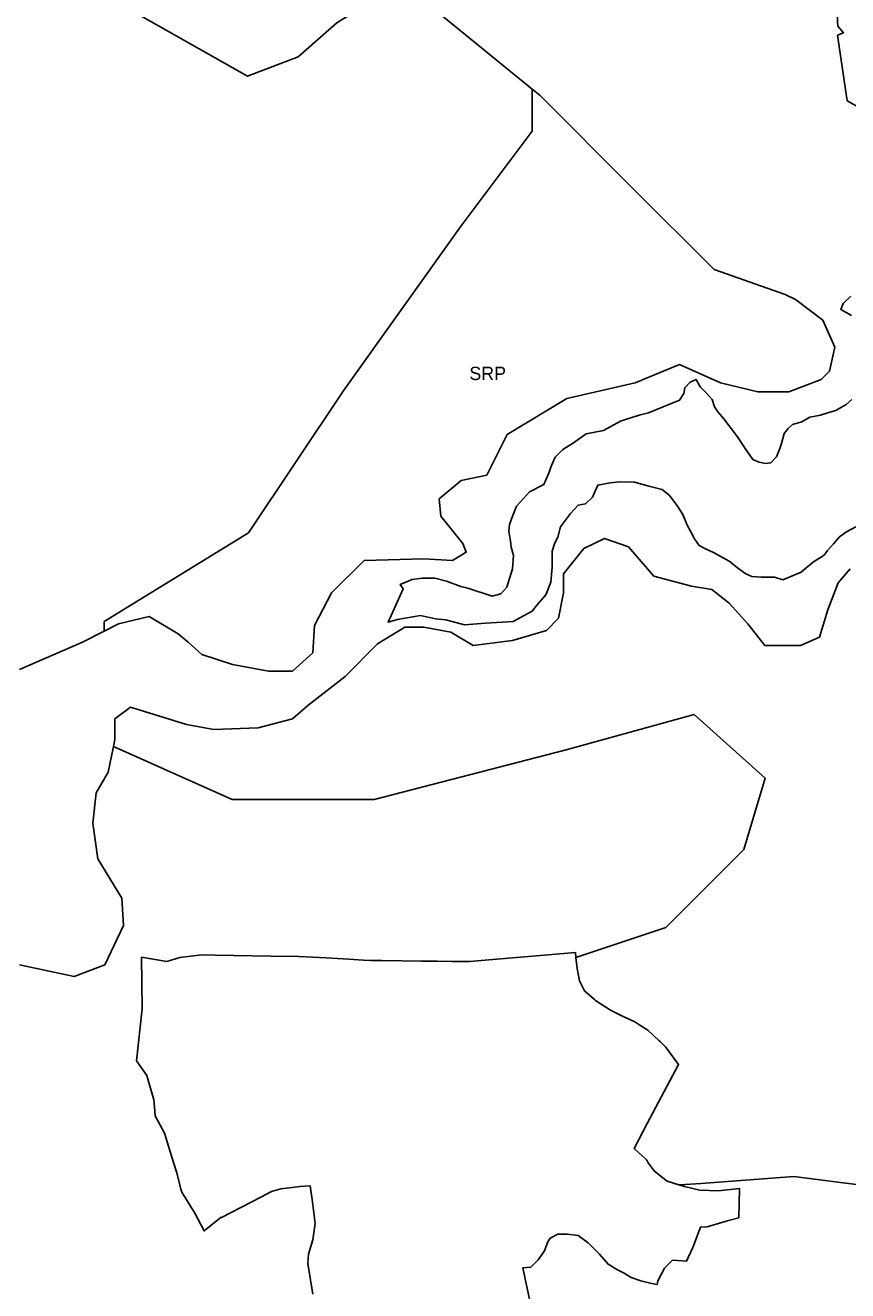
# Model space of a CAD drawing. Extents: x 598968 to 613553, y 4409678 to 4430833.
# Drawn here: x 604005 to 604746, y 4417266 to 4418405 of the extents above; entities that cross this region are included whole.
import ezdxf

# ---------------------------------------------------------------- set-up
doc = ezdxf.new("R2010")
doc.units = 0
for name, color, linetype in [("Hortal d'Oci", 7, 'Continuous'), ('Sòl Rústic Comú', 7, 'Continuous'), ('Sòl Rústic Protegit', 7, 'Continuous')]:
    doc.layers.add(name, color=color, linetype=linetype)

msp = doc.modelspace()

# ---------------------------------------------------------------- linework, layer by layer
at = {"layer": "Hortal d'Oci"}
msp.add_lwpolyline([(604460.4085, 4417252.3528), (604453.0009, 4417286.3984), (604460.2827, 4417287.1264), (604466.8363, 4417293.68), (604472.6617, 4417301.69), (604475.5743, 4417309.7), (604477.7589, 4417312.9766), (604484.6765, 4417316.6176), (604493.0505, 4417316.6176), (604502.8809, 4417315.5254), (604511.9831, 4417308.9718), (604522.1775, 4417298.7772), (604529.8233, 4417289.675), (604538.1975, 4417284.5778), (604544.3869, 4417281.6652), (604550.5763, 4417277.6602), (604559.3145, 4417274.7476), (604567.6885, 4417272.563), (604573.8609, 4417271.4738), (604573.9283, 4417271.487), (604574.6701, 4417274.6502), (604580.7801, 4417286.2202), (604587.8701, 4417293.3802), (604596.8603, 4417292.6738), (604600.5473, 4417292.3842), (604606.1601, 4417304.7102), (604613.0331, 4417323.0408), (604619.0001, 4417323.2402), (604638.3127, 4417329.1284), (604647.5515, 4417331.462), (604648.0901, 4417357.8902), (604628.9601, 4417355.7202), (604612.4101, 4417356.4702), (604598.5797, 4417359.5884), (604593.6145, 4417361.1264), (604593.5683, 4417361.1408), (604583.1387, 4417364.3716), (604577.9355, 4417368.4562), (604571.2301, 4417373.7202), (604565.9661, 4417381.0074), (604564.8291, 4417383.4706), (604563.1901, 4417384.8502), (604554.1349, 4417393.0424), (604553.3097, 4417393.789), (604553.3221, 4417393.8124), (604565.1861, 4417416.3564), (604593.3301, 4417469.5902), (604581.6239, 4417485.26), (604581.0141, 4417485.869), (604577.0349, 4417489.8438), (604575.7009, 4417491.1762), (604565.6777, 4417500.2778), (604557.6731, 4417505.5056), (604553.8319, 4417508.0144), (604553.4843, 4417508.1652), (604543.3529, 4417512.5652), (604531.9627, 4417518.4812), (604518.5181, 4417527.1454), (604517.8389, 4417527.583), (604517.4903, 4417527.8964), (604508.7267, 4417535.7746), (604504.1709, 4417544.8762), (604501.8927, 4417555.7984), (604500.8815, 4417565.7416), (604500.4301, 4417570.1818), (604475.7799, 4417568.1008), (604425.9597, 4417563.8946), (604405.0601, 4417562.1302), (604389.6199, 4417562.3126), (604376.0301, 4417562.4732), (604361.8897, 4417562.6404), (604326.0401, 4417563.0728), (604316.0219, 4417563.164), (604309.6901, 4417563.2702), (604296.3491, 4417564.2118), (604276.1201, 4417565.6396), (604251.4001, 4417566.8502), (604226.1501, 4417567.1282), (604176.1599, 4417567.9268), (604164.1701, 4417568.3602), (604144.1501, 4417565.9002), (604132.6601, 4417562.2502), (604109.8301, 4417566.0702), (604110.3121, 4417519.6512), (604105.1901, 4417472.8002), (604114.4801, 4417459.5802), (604121.0101, 4417437.6202), (604121.7467, 4417427.83), (604122.0801, 4417423.4002), (604130.4801, 4417407.5702), (604138.7155, 4417381.1888), (604141.5901, 4417371.9802), (604145.2431, 4417357.376), (604145.9401, 4417354.5902), (604157.9269, 4417335.6482), (604166.1615, 4417319.652), (604181.5201, 4417332.0002), (604181.8167, 4417331.602), (604217.3009, 4417349.9776), (604226.9183, 4417355.107), (604235.2533, 4417357.6716), (604252.5647, 4417359.595), (604261.5409, 4417360.2362), (604263.4643, 4417348.0542), (604266.0291, 4417326.2548), (604264.1055, 4417311.508), (604260.2585, 4417298.6848), (604259.6175, 4417290.3498), (604264.1055, 4417262.7798)], dxfattribs=at)
at = {"layer": 'Sòl Rústic Comú'}
for points in [[(603999.9115, 4417825.1932), (604056.7247, 4417849.6934), (604076.0375, 4417859.6934), (604076.0375, 4417868.1934), (604206.1641, 4417948.1936), (604291.2905, 4418075.6938), (604397.6673, 4418224.6942), (604461.4807, 4418309.6944), (604461.4809, 4418347.6944), (604377.0427, 4418416.1944), (604320.4797, 4418429.1942), (604285.6667, 4418407.1942), (604250.7913, 4418376.6942), (604205.1033, 4418359.194), (603943.8511, 4418507.1938)], [(604264.1055, 4417262.7798), (604259.6175, 4417290.3498), (604260.2585, 4417298.6848), (604264.1055, 4417311.508), (604266.0291, 4417326.2548), (604263.4643, 4417348.0542), (604261.5409, 4417360.2362), (604252.5647, 4417359.595), (604235.2533, 4417357.6716), (604226.9183, 4417355.107), (604217.3009, 4417349.9776), (604181.8167, 4417331.602), (604181.5201, 4417332.0002), (604166.1615, 4417319.652), (604157.9269, 4417335.6482), (604145.9401, 4417354.5902), (604145.2431, 4417357.376), (604141.5901, 4417371.9802), (604138.7155, 4417381.1888), (604130.4801, 4417407.5702), (604122.0801, 4417423.4002), (604121.7467, 4417427.83), (604121.0101, 4417437.6202), (604114.4801, 4417459.5802), (604105.1901, 4417472.8002), (604110.3121, 4417519.6512), (604109.8301, 4417566.0702), (604132.6601, 4417562.2502), (604144.1501, 4417565.9002), (604164.1701, 4417568.3602), (604176.1599, 4417567.9268), (604226.1501, 4417567.1282), (604251.4001, 4417566.8502), (604276.1201, 4417565.6396), (604296.3491, 4417564.2118), (604309.6901, 4417563.2702), (604316.0219, 4417563.164), (604326.0401, 4417563.0728), (604361.8897, 4417562.6404), (604376.0301, 4417562.4732), (604389.6199, 4417562.3126), (604405.0601, 4417562.1302), (604425.9597, 4417563.8946), (604475.7799, 4417568.1008), (604500.4301, 4417570.1818), (604500.8815, 4417565.7416), (604581.7917, 4417592.6938), (604652.1677, 4417663.194), (604671.4181, 4417727.194), (604607.3553, 4417784.694), (604492.1665, 4417752.6938), (604319.2895, 4417708.1936), (604191.2881, 4417708.1934), (604084.4747, 4417755.6934), (604079.7245, 4417732.6932), (604069.0369, 4417714.1932), (604065.9117, 4417686.6932), (604070.5367, 4417654.6932), (604092.0367, 4417619.1932), (604093.5991, 4417594.6932), (604076.6613, 4417559.1932), (604049.0361, 4417548.693), (603999.9105, 4417559.193)], [(604793.0431, 4417356.194), (604696.9797, 4417368.6938), (604613.7913, 4417362.1936), (604594.3417, 4417361.181), (604593.6117, 4417361.143), (604593.5683, 4417361.1408), (604593.6145, 4417361.1264), (604598.5797, 4417359.5884), (604612.4101, 4417356.4702), (604628.9601, 4417355.7202), (604648.0901, 4417357.8902), (604647.5515, 4417331.462), (604638.3127, 4417329.1284), (604619.0001, 4417323.2402), (604613.0331, 4417323.0408), (604606.1601, 4417304.7102), (604600.5473, 4417292.3842), (604596.8603, 4417292.6738), (604587.8701, 4417293.3802), (604580.7801, 4417286.2202), (604574.6701, 4417274.6502), (604573.9283, 4417271.487), (604573.8609, 4417271.4738), (604567.6885, 4417272.563), (604559.3145, 4417274.7476), (604550.5763, 4417277.6602), (604544.3869, 4417281.6652), (604538.1975, 4417284.5778), (604529.8233, 4417289.675), (604522.1775, 4417298.7772), (604511.9831, 4417308.9718), (604502.8809, 4417315.5254), (604493.0505, 4417316.6176), (604484.6765, 4417316.6176), (604477.7589, 4417312.9766), (604475.5743, 4417309.7), (604472.6617, 4417301.69), (604466.8363, 4417293.68), (604460.2827, 4417287.1264), (604453.0009, 4417286.3984), (604460.4085, 4417252.3528)]]:
    msp.add_lwpolyline(points, dxfattribs=at)
at = {"layer": 'Sòl Rústic Protegit'}
for points in [[(603943.8511, 4418507.1938), (604205.1033, 4418359.194), (604250.7913, 4418376.6942), (604285.6667, 4418407.1942)], [(604377.0427, 4418416.1944), (604461.4809, 4418347.6944), (604468.4809, 4418342.1944), (604551.2315, 4418259.1944), (604625.2319, 4418185.1944), (604689.2325, 4418162.6946), (604698.6077, 4418158.1946), (604723.1703, 4418139.6946), (604733.9203, 4418115.1946), (604729.2951, 4418093.6946), (604721.6075, 4418086.1944), (604692.4823, 4418075.1944), (604664.7945, 4418075.1944), (604631.0441, 4418083.1944), (604594.1689, 4418099.6944), (604554.2309, 4418083.1942), (604492.8551, 4418069.1942), (604439.1045, 4418036.694), (604420.6667, 4418000.194), (604397.6039, 4417995.194), (604377.6661, 4417978.694), (604379.1661, 4417963.194), (604399.1661, 4417938.694), (604402.2287, 4417930.694), (604389.9161, 4417923.1938), (604363.8533, 4417924.6938), (604310.1027, 4417923.1938), (604280.9147, 4417894.1938), (604265.5395, 4417864.6936), (604264.0393, 4417840.1936), (604245.6017, 4417823.6936), (604224.1015, 4417823.6936), (604191.8511, 4417829.6936), (604164.2259, 4417838.6934), (604151.9133, 4417849.6934), (604142.7257, 4417857.1934), (604116.6005, 4417872.6934), (604088.9751, 4417866.1934), (604076.0375, 4417859.6934), (604056.7247, 4417849.6934), (603999.9115, 4417825.1932)], [(604761.8589, 4418327.6948), (604745.1713, 4418337.1948), (604736.5465, 4418396.1948), (604741.7965, 4418398.1948), (604736.7339, 4418404.1948), (604736.0465, 4418414.6948)], [(604736.0465, 4418414.6948), (604736.7339, 4418404.1948), (604741.7965, 4418398.1948), (604736.5465, 4418396.1948), (604745.1713, 4418337.1948), (604761.8589, 4418327.6948)], [(604748.9205, 4418143.6946), (604739.5455, 4418149.1946), (604741.4831, 4418154.6946), (604748.5457, 4418161.1946)], [(604748.5457, 4418161.1946), (604741.4831, 4418154.6946), (604739.5455, 4418149.1946), (604748.9205, 4418143.6946)], [(604752.9199, 4417953.6944), (604744.6697, 4417949.1944), (604738.1697, 4417944.6944), (604732.9197, 4417938.1944), (604727.4821, 4417932.1944), (604724.4195, 4417928.1944), (604714.7943, 4417922.1944), (604708.2317, 4417916.6944), (604703.7943, 4417912.6944), (604687.1691, 4417905.6942), (604679.7315, 4417908.1942), (604667.7313, 4417908.1942), (604659.3563, 4417908.6942), (604653.9813, 4417911.1942), (604647.5437, 4417915.6942), (604638.9185, 4417922.6942), (604625.4809, 4417930.1942), (604616.9185, 4417934.1942), (604611.8559, 4417936.6942), (604607.7933, 4417942.6942), (604604.4183, 4417949.1942), (604600.9809, 4417955.1942), (604597.2309, 4417964.6942), (604593.0433, 4417971.1942), (604589.1683, 4417976.6942), (604584.7933, 4417982.1942), (604578.4183, 4417987.1942), (604566.5431, 4417990.1942), (604553.6055, 4417993.6942), (604540.3553, 4417994.1942), (604531.7927, 4417993.1942), (604520.5427, 4417991.1942), (604515.9175, 4417980.1942), (604509.4799, 4417974.194), (604502.7923, 4417973.194), (604496.1047, 4417965.694), (604487.1671, 4417953.694), (604484.6671, 4417944.194), (604482.0421, 4417939.194), (604479.4169, 4417931.694), (604479.4795, 4417917.194), (604478.2293, 4417903.694), (604473.6667, 4417892.194), (604466.1041, 4417883.194), (604461.4791, 4417877.694), (604444.2913, 4417868.194), (604419.5411, 4417866.6938), (604400.4783, 4417865.1938), (604383.6657, 4417869.6938), (604374.6031, 4417870.6938), (604360.9781, 4417873.6938), (604340.3527, 4417870.1938), (604331.7901, 4417867.6938), (604345.2279, 4417897.6938), (604342.7279, 4417901.6938), (604353.5405, 4417906.1938), (604362.6031, 4417907.1938), (604373.7283, 4417907.1938), (604384.3533, 4417904.6938), (604397.3535, 4417899.6938), (604403.7285, 4417898.1938), (604425.4787, 4417891.1938), (604433.2913, 4417893.194), (604438.6039, 4417899.194), (604443.7291, 4417915.694), (604444.6665, 4417927.694), (604442.5415, 4417935.194), (604441.9167, 4417940.694), (604440.4167, 4417949.694), (604440.9791, 4417955.694), (604443.4167, 4417962.194), (604447.5417, 4417972.194), (604453.8543, 4417979.194), (604458.9795, 4417985.194), (604472.0421, 4417991.694), (604476.2923, 4418001.194), (604478.7923, 4418008.694), (604482.1049, 4418016.194), (604489.1049, 4418023.1942), (604498.7301, 4418029.1942), (604510.1677, 4418037.1942), (604525.7929, 4418040.1942), (604541.1681, 4418048.6942), (604545.6057, 4418050.1942), (604557.8557, 4418054.1942), (604566.3559, 4418056.1942), (604594.2937, 4418067.6942), (604597.9813, 4418073.6944), (604598.8563, 4418078.6944), (604603.6689, 4418083.6944), (604609.2315, 4418086.1944), (604612.9189, 4418079.6944), (604618.2315, 4418074.1944), (604623.6065, 4418068.1944), (604625.7315, 4418061.6944), (604628.5439, 4418057.1944), (604634.1065, 4418050.6944), (604643.6691, 4418038.1944), (604646.8567, 4418033.6944), (604653.2941, 4418024.1944), (604660.0441, 4418014.1944), (604665.9817, 4418011.6944), (604671.7317, 4418010.6944), (604676.4819, 4418011.1944), (604681.4819, 4418016.6944), (604684.6069, 4418024.1944), (604685.9195, 4418028.6944), (604688.3571, 4418037.6944), (604691.8571, 4418042.1944), (604695.9197, 4418045.6944), (604704.1697, 4418048.1944), (604711.4199, 4418052.1944), (604721.1699, 4418054.1944), (604729.5451, 4418056.6944), (604734.9827, 4418058.1944), (604740.0451, 4418061.1944), (604744.3577, 4418063.6944), (604749.2953, 4418068.1946)], [(604749.2953, 4418068.1946), (604744.3577, 4418063.6944), (604740.0451, 4418061.1944), (604734.9827, 4418058.1944), (604729.5451, 4418056.6944), (604721.1699, 4418054.1944), (604711.4199, 4418052.1944), (604704.1697, 4418048.1944), (604695.9197, 4418045.6944), (604691.8571, 4418042.1944), (604688.3571, 4418037.6944), (604685.9195, 4418028.6944), (604684.6069, 4418024.1944), (604681.4819, 4418016.6944), (604676.4819, 4418011.1944), (604671.7317, 4418010.6944), (604665.9817, 4418011.6944), (604660.0441, 4418014.1944), (604653.2941, 4418024.1944), (604646.8567, 4418033.6944), (604643.6691, 4418038.1944), (604634.1065, 4418050.6944), (604628.5439, 4418057.1944), (604625.7315, 4418061.6944), (604623.6065, 4418068.1944), (604618.2315, 4418074.1944), (604612.9189, 4418079.6944), (604609.2315, 4418086.1944), (604603.6689, 4418083.6944), (604598.8563, 4418078.6944), (604597.9813, 4418073.6944), (604594.2937, 4418067.6942), (604566.3559, 4418056.1942), (604557.8557, 4418054.1942), (604545.6057, 4418050.1942), (604541.1681, 4418048.6942), (604525.7929, 4418040.1942), (604510.1677, 4418037.1942), (604498.7301, 4418029.1942), (604489.1049, 4418023.1942), (604482.1049, 4418016.194), (604478.7923, 4418008.694), (604476.2923, 4418001.194), (604472.0421, 4417991.694), (604458.9795, 4417985.194), (604453.8543, 4417979.194), (604447.5417, 4417972.194), (604443.4167, 4417962.194), (604440.9791, 4417955.694), (604440.4167, 4417949.694), (604441.9167, 4417940.694), (604442.5415, 4417935.194), (604444.6665, 4417927.694), (604443.7291, 4417915.694), (604438.6039, 4417899.194), (604433.2913, 4417893.194), (604425.4787, 4417891.1938), (604403.7285, 4417898.1938), (604397.3535, 4417899.6938), (604384.3533, 4417904.6938), (604373.7283, 4417907.1938), (604362.6031, 4417907.1938), (604353.5405, 4417906.1938), (604342.7279, 4417901.6938), (604345.2279, 4417897.6938), (604331.7901, 4417867.6938), (604340.3527, 4417870.1938), (604360.9781, 4417873.6938), (604374.6031, 4417870.6938), (604383.6657, 4417869.6938), (604400.4783, 4417865.1938), (604419.5411, 4417866.6938), (604444.2913, 4417868.194), (604461.4791, 4417877.694), (604466.1041, 4417883.194), (604473.6667, 4417892.194), (604478.2293, 4417903.694), (604479.4795, 4417917.194), (604479.4169, 4417931.694), (604482.0421, 4417939.194), (604484.6671, 4417944.194), (604487.1671, 4417953.694), (604496.1047, 4417965.694), (604502.7923, 4417973.194), (604509.4799, 4417974.194), (604515.9175, 4417980.1942), (604520.5427, 4417991.1942), (604531.7927, 4417993.1942), (604540.3553, 4417994.1942), (604553.6055, 4417993.6942), (604566.5431, 4417990.1942), (604578.4183, 4417987.1942), (604584.7933, 4417982.1942), (604589.1683, 4417976.6942), (604593.0433, 4417971.1942), (604597.2309, 4417964.6942), (604600.9809, 4417955.1942), (604604.4183, 4417949.1942), (604607.7933, 4417942.6942), (604611.8559, 4417936.6942), (604616.9185, 4417934.1942), (604625.4809, 4417930.1942), (604638.9185, 4417922.6942), (604647.5437, 4417915.6942), (604653.9813, 4417911.1942), (604659.3563, 4417908.6942), (604667.7313, 4417908.1942), (604679.7315, 4417908.1942), (604687.1691, 4417905.6942), (604703.7943, 4417912.6944), (604708.2317, 4417916.6944), (604714.7943, 4417922.1944), (604724.4195, 4417928.1944), (604727.4821, 4417932.1944), (604732.9197, 4417938.1944), (604738.1697, 4417944.6944), (604744.6697, 4417949.1944), (604752.9199, 4417953.6944)], [(603999.9105, 4417559.193), (604049.0361, 4417548.693), (604076.6613, 4417559.1932), (604093.5991, 4417594.6932), (604092.0367, 4417619.1932), (604070.5367, 4417654.6932), (604065.9117, 4417686.6932), (604069.0369, 4417714.1932), (604079.7245, 4417732.6932), (604084.4747, 4417755.6934), (604085.9123, 4417762.1934), (604085.9123, 4417780.6934), (604099.7249, 4417791.1934), (604150.4129, 4417775.6934), (604174.9757, 4417771.1934), (604214.9137, 4417772.6934), (604245.6015, 4417780.6936), (604259.4141, 4417792.6936), (604293.2271, 4417818.6936), (604322.3525, 4417848.1938), (604346.9779, 4417863.1938), (604363.8531, 4417863.1938), (604388.4157, 4417858.6938), (604408.3535, 4417846.6938), (604443.6663, 4417851.1938), (604474.4167, 4417860.194), (604485.1669, 4417871.194), (604489.7295, 4417894.194), (604489.7295, 4417911.194), (604508.1673, 4417934.194), (604526.6051, 4417943.194), (604548.1053, 4417935.6942), (604571.1679, 4417909.1942), (604604.9181, 4417900.1942), (604623.3559, 4417897.1942), (604638.7309, 4417884.6942), (604655.6061, 4417866.1942), (604670.9811, 4417846.6942), (604703.2315, 4417846.6942), (604720.1067, 4417854.1942), (604727.7943, 4417878.6944), (604736.9821, 4417903.1944), (604747.7323, 4417915.6944)], [(604747.7323, 4417915.6944), (604736.9821, 4417903.1944), (604727.7943, 4417878.6944), (604720.1067, 4417854.1942), (604703.2315, 4417846.6942), (604670.9811, 4417846.6942), (604655.6061, 4417866.1942), (604638.7309, 4417884.6942), (604623.3559, 4417897.1942), (604604.9181, 4417900.1942), (604571.1679, 4417909.1942), (604548.1053, 4417935.6942), (604526.6051, 4417943.194), (604508.1673, 4417934.194), (604489.7295, 4417911.194), (604489.7295, 4417894.194), (604485.1669, 4417871.194), (604474.4167, 4417860.194), (604443.6663, 4417851.1938), (604408.3535, 4417846.6938), (604388.4157, 4417858.6938), (604363.8531, 4417863.1938), (604346.9779, 4417863.1938), (604322.3525, 4417848.1938), (604293.2271, 4417818.6936), (604259.4141, 4417792.6936), (604245.6015, 4417780.6936), (604214.9137, 4417772.6934), (604174.9757, 4417771.1934), (604150.4129, 4417775.6934), (604099.7249, 4417791.1934), (604085.9123, 4417780.6934), (604085.9123, 4417762.1934), (604084.4747, 4417755.6934), (604191.2881, 4417708.1934), (604319.2895, 4417708.1936), (604492.1665, 4417752.6938), (604607.3553, 4417784.694), (604671.4181, 4417727.194), (604652.1677, 4417663.194), (604581.7917, 4417592.6938), (604500.8815, 4417565.7416), (604501.8927, 4417555.7984), (604504.1709, 4417544.8762), (604508.7267, 4417535.7746), (604517.4903, 4417527.8964), (604517.8389, 4417527.583), (604518.5181, 4417527.1454), (604531.9627, 4417518.4812), (604543.3529, 4417512.5652), (604553.4843, 4417508.1652), (604553.8319, 4417508.0144), (604557.6731, 4417505.5056), (604565.6777, 4417500.2778), (604575.7009, 4417491.1762), (604577.0349, 4417489.8438), (604581.0141, 4417485.869), (604581.6239, 4417485.26), (604593.3301, 4417469.5902), (604565.1861, 4417416.3564), (604553.3221, 4417393.8124), (604553.3097, 4417393.789), (604554.1349, 4417393.0424), (604563.1901, 4417384.8502), (604564.8291, 4417383.4706), (604565.9661, 4417381.0074), (604571.2301, 4417373.7202), (604577.9355, 4417368.4562), (604583.1387, 4417364.3716), (604593.5683, 4417361.1408), (604593.6117, 4417361.143), (604594.3417, 4417361.181), (604613.7913, 4417362.1936), (604696.9797, 4417368.6938), (604793.0431, 4417356.194)]]:
    msp.add_lwpolyline(points, dxfattribs=at)
msp.add_lwpolyline([(604076.0375, 4417859.6934), (604088.9751, 4417866.1934), (604116.6005, 4417872.6934), (604142.7257, 4417857.1934), (604151.9133, 4417849.6934), (604164.2259, 4417838.6934), (604191.8511, 4417829.6936), (604224.1015, 4417823.6936), (604245.6017, 4417823.6936), (604264.0393, 4417840.1936), (604265.5395, 4417864.6936), (604280.9147, 4417894.1938), (604310.1027, 4417923.1938), (604363.8533, 4417924.6938), (604389.9161, 4417923.1938), (604402.2287, 4417930.694), (604399.1661, 4417938.694), (604379.1661, 4417963.194), (604377.6661, 4417978.694), (604397.6039, 4417995.194), (604420.6667, 4418000.194), (604439.1045, 4418036.694), (604492.8551, 4418069.1942), (604554.2309, 4418083.1942), (604594.1689, 4418099.6944), (604631.0441, 4418083.1944), (604664.7945, 4418075.1944), (604692.4823, 4418075.1944), (604721.6075, 4418086.1944), (604729.2951, 4418093.6946), (604733.9203, 4418115.1946), (604723.1703, 4418139.6946), (604698.6077, 4418158.1946), (604689.2325, 4418162.6946), (604625.2319, 4418185.1944), (604551.2315, 4418259.1944), (604468.4809, 4418342.1944), (604461.4809, 4418347.6944), (604461.4807, 4418309.6944), (604397.6673, 4418224.6942), (604291.2905, 4418075.6938), (604206.1641, 4417948.1936), (604076.0375, 4417868.1934)], close=True, dxfattribs=at)

# ---------------------------------------------------------------- texts
msp.add_text('SRP', height=12, dxfattribs=at).set_placement((604404.9789, 4418085.694))

doc.saveas('drawing.dxf')
